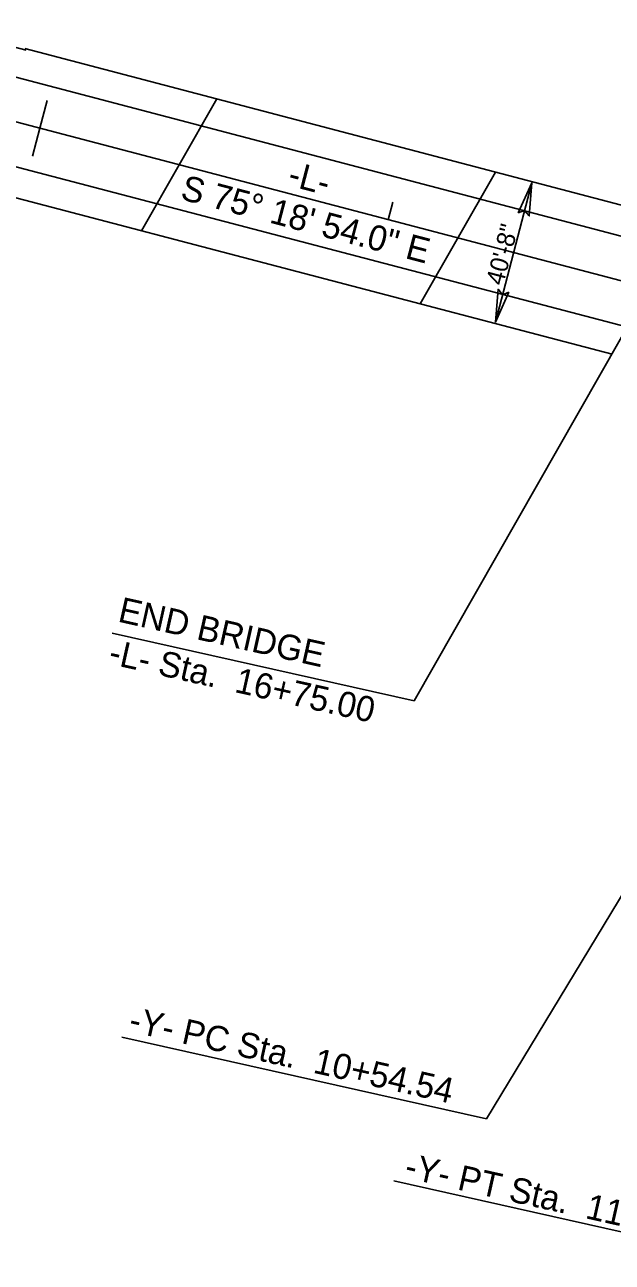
# Model space of a CAD drawing. Extents: x 1784740 to 1786163, y 841056 to 841833.
# Drawn here: x 1785454.6 to 1785617.7, y 841169.1 to 841512.6 of the extents above; entities that cross this region are included whole.
import ezdxf

# ---------------------------------------------------------------- set-up
doc = ezdxf.new("R2010")
doc.units = 0
for name, color, linetype in [('Prop Dimension', 7, 'Continuous'), ('Prop DSN Text', 7, 'Continuous'), ('Prop EOT', 7, 'Continuous'), ('Prop Horizontal Alignment', 7, 'Continuous'), ('Prop Horizontal Alignment Direction Label', 7, 'Continuous'), ('Prop Horizontal Alignment Station Label', 7, 'Continuous'), ('Prop Horizontal Alignment Tick Large', 7, 'Continuous'), ('Prop Horizontal Alignment Tick Small', 7, 'Continuous'), ('Prop Roadway Bridge', 7, 'Continuous'), ('Prop Structure Anchor Unit CELL', 7, 'Continuous'), ('Prop Terminator CELL', 7, 'Continuous')]:
    doc.layers.add(name, color=color, linetype=linetype)

msp = doc.modelspace()

# ---------------------------------------------------------------- linework, layer by layer
at = {"layer": 'Prop Dimension'}
msp.add_line((1785595.42, 841468.68), (1785585.28, 841429.98), dxfattribs=at)
at = {"layer": 'Prop DSN Text'}
for p, q in [((1785562.76, 841324.91), (1785628.04, 841439.45)), ((1785478.85, 841343.73), (1785562.76, 841324.91))]:
    msp.add_line(p, q, dxfattribs=at)
at = {"layer": 'Prop EOT'}
for p, q in [((1785396.43, 841512.55), (1785733.71, 841424.16)), ((1785390.34, 841489.34), (1785642.41, 841423.28))]:
    msp.add_line(p, q, dxfattribs=at)
at = {"layer": 'Prop Horizontal Alignment'}
msp.add_line((1785393.39, 841500.94), (1785730.66, 841412.56), dxfattribs=at)
at = {"layer": 'Prop Horizontal Alignment Station Label'}
for p, q in [((1785680, 841369.45), (1785582.83, 841208.91)), ((1785582.83, 841208.91), (1785481.5, 841231.63)), ((1785658, 841169.14), (1785557.09, 841191.77))]:
    msp.add_line(p, q, dxfattribs=at)
at = {"layer": 'Prop Horizontal Alignment Tick Large'}
for q in [(1785460.79, 841491.55), (1785456.73, 841476.07)]:
    msp.add_line((1785458.76, 841483.81), q, dxfattribs=at)
at = {"layer": 'Prop Horizontal Alignment Tick Small'}
msp.add_line((1785555.49, 841458.46), (1785556.76, 841463.3), dxfattribs=at)
at = {"layer": 'Prop Roadway Bridge'}
for p, q in [((1785454.59, 841505.93), (1785638.38, 841457.76)), ((1785507.88, 841491.96), (1785487.03, 841455.38)), ((1785585.27, 841471.68), (1785564.42, 841435.1)), ((1785433.91, 841469.3), (1785617.71, 841421.14))]:
    msp.add_line(p, q, dxfattribs=at)
at = {"layer": 'Prop Structure Anchor Unit CELL'}
msp.add_line((1785454.97, 841505.48), (1785436.83, 841510.23), dxfattribs=at)
at = {"layer": 'Prop Terminator CELL'}
for points in [[(1785591.63, 841460.36), (1785595.42, 841468.68), (1785594.67, 841459.52), (1785593.41, 841461.03)], [(1785589.06, 841438.3), (1785585.28, 841429.98), (1785586.02, 841439.14), (1785587.28, 841437.62)]]:
    msp.add_lwpolyline(points, close=True, dxfattribs=at)

# ---------------------------------------------------------------- texts
at = {"layer": 'Prop Dimension'}
msp.add_text('40\'-8"', height=5, rotation=75.315, dxfattribs=at).set_placement((1785587.4, 841439.97))
at = {"layer": 'Prop DSN Text'}
for s, p in [('END BRIDGE', (1785480.16, 841346.97)), ('-L- Sta.  16+75.00', (1785477.54, 841335.27))]:
    msp.add_text(s, height=7, rotation=347.3599, dxfattribs=at).set_placement(p)
at = {"layer": 'Prop Horizontal Alignment Direction Label'}
for s, p in [('-L-', (1785527.28, 841468.06)), ('S 75%%d 18\' 54.0" E', (1785497.5, 841464.19))]:
    msp.add_text(s, height=7, rotation=345.315, dxfattribs=at).set_placement(p)
at = {"layer": 'Prop Horizontal Alignment Station Label'}
for s, p in [('-Y- PC Sta.  10+54.54', (1785483.12, 841233.27)), ('-Y- PT Sta.  11+24.41', (1785559.75, 841192.67))]:
    msp.add_text(s, height=7, rotation=347.3599, dxfattribs=at).set_placement(p)

doc.saveas('drawing.dxf')
